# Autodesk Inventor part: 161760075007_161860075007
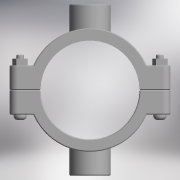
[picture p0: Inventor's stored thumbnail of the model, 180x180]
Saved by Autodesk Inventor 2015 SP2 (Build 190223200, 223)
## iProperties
Created: 2017-05
Part Number: 161760075007_161860075007
Material: Generic
Description: PLASSON DOUBLE SADDLE 75-3/4"
Document SubType Name: Modeling
Designer: KIM
Density: 1 g/cm^3
Appearance: Default
Author: KIM
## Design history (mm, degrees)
derived "16176.ipt"
feature "Solid1::16176.ipt"
feature "Solid2::16176.ipt"
tag "TaggingFeature1"
body "Solid1"
body "Solid2"
other parameters: "d0" = 93.75, "d1" = 122, "d2" = 37.5, "d3" = 75, "d4" = 98, "d5" = 0, "d6" = 6.1, "d7" = 122, "d8" = 0.1, "d10" = 0, "d11" = 0.75, "d20" = 0.75, "d23" = 0.75, "d37" = 8, "d38" = 45.5, "d39" = 0, "d40" = 3, "d41" = 5, "d42" = 0, "d43" = 6, "d44" = 3, "d45" = 0, "d46" = 0.75, "d52" = 24.117, "d53" = 19, "d54" = 0, "d57" = 0, "d58" = 81, "d60" = 0, "d63" = 8, "d66" = 82, "d68" = 31.3521, "d69" = 24.117, "d70" = 19, "d71" = 0, "d74" = 0, "d75" = 0.75, "d_" = 75, "G_" = 24.117, "A_" = 65, "L_" = 122, "L_1" = 98, "l_2" = 19
